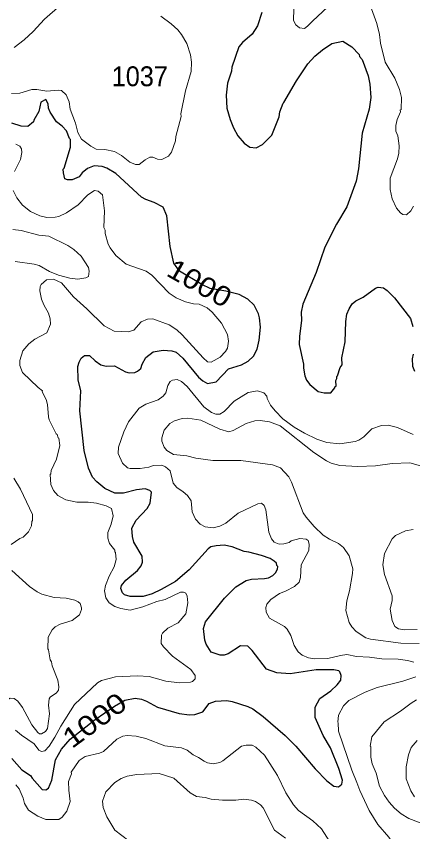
# Model space of a CAD drawing. Extents: x 447.8 to 473.9, y 7733.1 to 7760.8.
# Drawn here: x 462.937 to 464.533, y 7753.226 to 7756.505 of the extents above; entities that cross this region are included whole.
import ezdxf
from ezdxf.enums import TextEntityAlignment as Align

# ---------------------------------------------------------------- set-up
doc = ezdxf.new("R2010")
doc.units = 0
doc.header["$LTSCALE"] = 0.032
doc.layers.add('1', color=7, linetype='Continuous', lineweight=25)
doc.layers.add('2', color=7, linetype='Continuous', lineweight=13)
doc.layers.add('21', color=7, linetype='Continuous')
doc.layers.add('61', color=7, linetype='Continuous')

msp = doc.modelspace()

# ---------------------------------------------------------------- linework, layer by layer
at = {"layer": '1'}
for points in [[(463.9256, 7756.5203), (463.9084, 7756.4667), (463.8873, 7756.4334), (463.8473, 7756.4002), (463.8324, 7756.3825), (463.8049, 7756.3015), (463.803, 7756.2847), (463.7869, 7756.2363), (463.7813, 7756.1882), (463.7841, 7756.1364), (463.7977, 7756.0905), (463.8112, 7756.0567), (463.8288, 7756.0248), (463.8549, 7755.9948), (463.8768, 7755.9794), (463.9032, 7755.9761), (463.9278, 7755.9894), (463.966, 7756.028), (463.9952, 7756.1016), (463.998, 7756.1214), (464.011, 7756.1563), (464.0147, 7756.1584), (464.0653, 7756.2465), (464.1103, 7756.3138), (464.1388, 7756.3448), (464.1696, 7756.3705), (464.2079, 7756.3966), (464.2511, 7756.4048), (464.2874, 7756.3822), (464.3174, 7756.3522), (464.3193, 7756.3441), (464.3295, 7756.3312), (464.3536, 7756.2663), (464.3602, 7756.2331), (464.3649, 7756.1791), (464.3579, 7756.1316), (464.3297, 7756.0349), (464.3146, 7755.8917), (464.3057, 7755.8426), (464.2679, 7755.7396), (464.2266, 7755.67), (464.1795, 7755.577), (464.1444, 7755.4752), (464.0902, 7755.3476), (464.0836, 7755.3151), (464.0851, 7755.2827), (464.0772, 7755.219), (464.0765, 7755.1851), (464.0931, 7755.1063), (464.0932, 7755.09), (464.0993, 7755.0596), (464.1059, 7755.0426), (464.1181, 7755.0248), (464.1527, 7754.9962), (464.1769, 7754.9917), (464.2027, 7754.9917), (464.2193, 7755.0112), (464.2193, 7755.015), (464.2245, 7755.0186), (464.2231, 7755.0403), (464.2277, 7755.0487), (464.2272, 7755.0573), (464.2302, 7755.0593), (464.241, 7755.0924), (464.2486, 7755.1041), (464.2471, 7755.1323), (464.2615, 7755.1962), (464.2641, 7755.2777), (464.2679, 7755.308), (464.2768, 7755.3295), (464.2887, 7755.3489), (464.3038, 7755.361), (464.3339, 7755.3759), (464.3836, 7755.4127), (464.3935, 7755.4166), (464.4154, 7755.4133), (464.4307, 7755.4029), (464.4601, 7755.3736), (464.5237, 7755.2904), (464.5332, 7755.2586)], [(463.6703, 7755.0548), (463.6878, 7755.0393), (463.7072, 7755.0287), (463.7416, 7755.0359), (463.7911, 7755.0879), (463.8432, 7755.1032), (463.8701, 7755.118), (463.892, 7755.1386), (463.9063, 7755.167), (463.9145, 7755.2029), (463.9208, 7755.2551), (463.9162, 7755.2931), (463.9116, 7755.3093), (463.8951, 7755.344), (463.8695, 7755.368), (463.8347, 7755.3861), (463.781, 7755.4002), (463.7169, 7755.4114), (463.6846, 7755.4272), (463.5945, 7755.4811), (463.5715, 7755.5127), (463.556, 7755.5801), (463.5426, 7755.7024), (463.5281, 7755.7384), (463.492, 7755.7572), (463.4581, 7755.7686), (463.4414, 7755.7785), (463.3375, 7755.8731), (463.3015, 7755.8942), (463.2824, 7755.9014), (463.2503, 7755.9039), (463.2243, 7755.8927), (463.2023, 7755.8754), (463.1903, 7755.8598), (463.1617, 7755.8471), (463.1433, 7755.8478), (463.1327, 7755.8524), (463.1268, 7755.8753), (463.1263, 7755.8908), (463.1298, 7755.8945), (463.1553, 7755.9786), (463.1553, 7756.0101), (463.1513, 7756.014), (463.1398, 7756.0447), (463.1224, 7756.0642), (463.0985, 7756.0812), (463.0737, 7756.1193), (463.0671, 7756.136), (463.0654, 7756.1531), (463.0557, 7756.1705), (463.0361, 7756.1595), (463.0275, 7756.1226), (463.0073, 7756.0877), (463.0061, 7756.0806), (462.9838, 7756.0627), (462.9569, 7756.0634), (462.9196, 7756.0762)], [(463.4876, 7755.1561), (463.5285, 7755.1632), (463.5638, 7755.1601), (463.5804, 7755.1542), (463.608, 7755.1306), (463.6703, 7755.0548)], [(464.2284, 7753.8164), (464.2435, 7753.8359), (464.2446, 7753.854), (464.239, 7753.8696), (464.2354, 7753.8728), (464.215, 7753.8775), (464.1442, 7753.8775), (464.039, 7753.8608), (463.9854, 7753.8656), (463.9447, 7753.8792), (463.8861, 7753.9556), (463.8689, 7753.9727), (463.8402, 7753.9737), (463.7899, 7753.9415), (463.7741, 7753.9361), (463.7581, 7753.9361), (463.7222, 7753.9478), (463.7017, 7753.98), (463.696, 7753.996), (463.6901, 7754.0434), (463.699, 7754.0699), (463.7751, 7754.1655), (463.8208, 7754.2113), (463.8622, 7754.2359), (463.8846, 7754.2416), (463.9364, 7754.2439), (463.9529, 7754.2477), (463.9703, 7754.2572), (463.9808, 7754.2671), (463.989, 7754.2819), (463.9895, 7754.2934), (463.9858, 7754.2962), (463.9841, 7754.3056), (463.9753, 7754.3146), (463.9585, 7754.3248), (463.9236, 7754.3375), (463.8727, 7754.3507), (463.854, 7754.353), (463.8059, 7754.3714), (463.7741, 7754.3785), (463.7414, 7754.376), (463.7207, 7754.3714), (463.7098, 7754.3639), (463.6332, 7754.2793), (463.5777, 7754.2327), (463.5209, 7754.1998), (463.4843, 7754.1831), (463.4484, 7754.1717), (463.3959, 7754.1718), (463.3724, 7754.1792), (463.3652, 7754.1873), (463.3579, 7754.204), (463.36, 7754.2163), (463.3784, 7754.2384), (463.4256, 7754.2762), (463.4403, 7754.295), (463.4447, 7754.3097), (463.4439, 7754.3341), (463.4104, 7754.391), (463.4046, 7754.413), (463.4024, 7754.4473), (463.4199, 7754.4795), (463.4634, 7754.5262), (463.4763, 7754.5477), (463.4808, 7754.5919), (463.4751, 7754.5981), (463.4553, 7754.6052), (463.4207, 7754.6012), (463.3682, 7754.5877), (463.3333, 7754.5878), (463.2933, 7754.6066), (463.2607, 7754.6331), (463.2435, 7754.6517), (463.2278, 7754.6881), (463.2109, 7754.7587), (463.1923, 7754.9192), (463.1971, 7754.9997), (463.1868, 7755.0435), (463.185, 7755.0964), (463.1897, 7755.1142), (463.1988, 7755.1305), (463.2112, 7755.1408), (463.2313, 7755.1416), (463.2545, 7755.1195), (463.2771, 7755.1037), (463.2987, 7755.0984), (463.3323, 7755.0991), (463.3763, 7755.0755), (463.3911, 7755.0712), (463.414, 7755.0726), (463.4252, 7755.078), (463.439, 7755.0896), (463.4441, 7755.1059), (463.4583, 7755.1326), (463.4876, 7755.1561)], [(464.5348, 7755.1465), (464.5301, 7755.1282), (464.5317, 7755.0984), (464.5403, 7755.0779)], [(464.1719, 7753.6135), (464.1397, 7753.6856), (464.1397, 7753.7273), (464.1592, 7753.7622), (464.2036, 7753.7923), (464.2284, 7753.8164)], [(462.9196, 7753.52), (462.9589, 7753.4744), (462.9948, 7753.4519), (463.0004, 7753.4409), (463.0414, 7753.3958), (463.0558, 7753.3952), (463.0665, 7753.4018), (463.0805, 7753.4335), (463.0954, 7753.5148), (463.1197, 7753.5575), (463.1535, 7753.5984), (463.255, 7753.6769), (463.3318, 7753.7309), (463.3739, 7753.7554), (463.4153, 7753.7626), (463.4407, 7753.7591), (463.4612, 7753.7511), (463.5056, 7753.7264), (463.5927, 7753.7013), (463.6339, 7753.6956), (463.6552, 7753.6979), (463.6881, 7753.7087), (463.7138, 7753.7417), (463.7393, 7753.7517), (463.7841, 7753.7533), (463.8059, 7753.7502), (463.869, 7753.7299), (463.8893, 7753.7198), (463.9309, 7753.6894), (464.0197, 7753.6128), (464.0626, 7753.5706), (464.1402, 7753.4786), (464.1877, 7753.4304), (464.2158, 7753.4093), (464.2342, 7753.4072), (464.247, 7753.4172), (464.2503, 7753.4335), (464.2356, 7753.48), (464.2014, 7753.5641), (464.1719, 7753.6135)]]:
    msp.add_lwpolyline(points, dxfattribs=at)
at = {"layer": '2'}
for points in [[(463.1136, 7756.5484), (463.0509, 7756.4937), (463.0052, 7756.444), (462.9683, 7756.4103), (462.9286, 7756.3802)], [(464.0549, 7756.5353), (464.0532, 7756.4887), (464.0629, 7756.4715), (464.0777, 7756.4586), (464.0971, 7756.4564), (464.1095, 7756.4653), (464.129, 7756.4865), (464.2108, 7756.562)], [(464.3673, 7756.5354), (464.389, 7756.4767), (464.3993, 7756.4329), (464.4028, 7756.3979), (464.4216, 7756.3206), (464.4605, 7756.2571), (464.4799, 7756.2114), (464.4875, 7756.1792), (464.4859, 7756.1303), (464.4828, 7756.1281), (464.4842, 7756.1206), (464.4701, 7756.0902), (464.4652, 7756.0669), (464.4652, 7756.0429), (464.4724, 7756.0247), (464.4788, 7755.9846), (464.4772, 7755.9551), (464.4722, 7755.9318), (464.4419, 7755.8538), (464.4427, 7755.8086), (464.4508, 7755.7716), (464.4679, 7755.7342), (464.4839, 7755.7144), (464.4925, 7755.7079), (464.5085, 7755.7069), (464.526, 7755.7236), (464.5358, 7755.7412)], [(462.9175, 7756.1951), (462.9507, 7756.1963), (462.9995, 7756.2109), (463.0193, 7756.2109), (463.0597, 7756.2046), (463.105, 7756.2085), (463.1191, 7756.2064), (463.1376, 7756.1902), (463.1497, 7756.1612), (463.1539, 7756.1318), (463.1758, 7756.0758), (463.1842, 7756.0385), (463.199, 7756.0112), (463.2369, 7755.9827), (463.2592, 7755.9706), (463.2932, 7755.9696), (463.3323, 7755.9612), (463.3612, 7755.9455), (463.3941, 7755.9188), (463.4176, 7755.9097), (463.4324, 7755.9096), (463.4561, 7755.9287), (463.4743, 7755.9384), (463.4862, 7755.9383), (463.5061, 7755.9313), (463.5234, 7755.9298), (463.5496, 7755.9434), (463.5613, 7755.9585), (463.5785, 7756.0042), (463.58, 7756.0223), (463.601, 7756.1019), (463.5995, 7756.1132), (463.6188, 7756.2052), (463.6411, 7756.2831), (463.642, 7756.3213), (463.6379, 7756.3504), (463.6233, 7756.3956), (463.6019, 7756.4327), (463.5876, 7756.4512), (463.5604, 7756.4752), (463.519, 7756.5055)], [(462.9295, 7755.881), (462.9534, 7755.9291), (462.9597, 7755.9573), (462.9582, 7755.9718), (462.9516, 7755.9833), (462.9354, 7755.9913)], [(463.2948, 7755.6447), (463.2901, 7755.6566), (463.2916, 7755.7236), (463.2835, 7755.7876), (463.2666, 7755.8024), (463.2517, 7755.8054), (463.2245, 7755.7879), (463.1864, 7755.7466), (463.1388, 7755.7149), (463.1082, 7755.7006), (463.0933, 7755.697), (463.0601, 7755.6964), (463.0319, 7755.7027), (462.994, 7755.7208), (462.9619, 7755.7463), (462.9392, 7755.775), (462.9246, 7755.8047)], [(462.9232, 7755.6483), (462.9562, 7755.6435), (463.0274, 7755.6251), (463.0678, 7755.6207), (463.1451, 7755.5837), (463.1684, 7755.5678), (463.198, 7755.5414), (463.2273, 7755.4946), (463.2307, 7755.4805), (463.2279, 7755.459), (463.2168, 7755.454), (463.1847, 7755.4487), (463.1533, 7755.4524), (463.1069, 7755.464), (463.0712, 7755.4794), (463.0294, 7755.5028), (463.0091, 7755.5088), (462.9325, 7755.52)], [(463.3798, 7755.5088), (463.3376, 7755.543), (463.3147, 7755.574), (463.3074, 7755.5896), (463.2953, 7755.6321), (463.2948, 7755.6447)], [(463.536, 7754.16), (463.5027, 7754.152), (463.4466, 7754.1304), (463.3959, 7754.1173), (463.3575, 7754.1232), (463.3336, 7754.1323), (463.3115, 7754.1465), (463.2976, 7754.1664), (463.2917, 7754.1954), (463.2958, 7754.2157), (463.311, 7754.2538), (463.3315, 7754.2917), (463.3388, 7754.3206), (463.3365, 7754.3492), (463.3335, 7754.3522), (463.3332, 7754.3584), (463.3129, 7754.3858), (463.3061, 7754.4071), (463.3061, 7754.4298), (463.3187, 7754.4632), (463.3268, 7754.4968), (463.3203, 7754.5265), (463.2986, 7754.5373), (463.2599, 7754.5476), (463.2262, 7754.5516), (463.181, 7754.5516), (463.1364, 7754.5612), (463.1043, 7754.578), (463.0872, 7754.5984), (463.0758, 7754.6229), (463.0736, 7754.6627), (463.0765, 7754.666), (463.0777, 7754.6786), (463.0983, 7754.725), (463.1128, 7754.7797), (463.1087, 7754.8088), (463.1057, 7754.8101), (463.1015, 7754.8241), (463.0978, 7754.826), (463.0693, 7754.8826), (463.0662, 7754.8943), (463.0631, 7754.9444), (463.0573, 7754.9644), (463.0418, 7754.9954), (463.0426, 7754.9988), (463.0251, 7755.0122), (462.962, 7755.073), (462.951, 7755.1012), (462.9518, 7755.1208), (462.9639, 7755.1595), (462.9876, 7755.1887), (463.0116, 7755.2069), (463.0595, 7755.2328), (463.0751, 7755.2668), (463.0736, 7755.2888), (463.067, 7755.3118), (463.0478, 7755.3455), (463.0389, 7755.3684), (463.032, 7755.4017), (463.0336, 7755.4194), (463.0372, 7755.4273), (463.0587, 7755.4462), (463.0875, 7755.4489), (463.1187, 7755.4332), (463.1668, 7755.3779), (463.2205, 7755.329), (463.2903, 7755.2603), (463.3306, 7755.2395), (463.3875, 7755.2362), (463.4105, 7755.2438), (463.4393, 7755.277), (463.4654, 7755.2875), (463.4872, 7755.2883), (463.5529, 7755.265), (463.5837, 7755.244), (463.6043, 7755.2249), (463.6896, 7755.1317), (463.7072, 7755.1161), (463.722, 7755.1145), (463.7574, 7755.1344), (463.7795, 7755.1574), (463.7869, 7755.1708), (463.7918, 7755.1993), (463.7867, 7755.2257), (463.7638, 7755.2709), (463.7262, 7755.3162), (463.7058, 7755.3328), (463.6738, 7755.3482), (463.6507, 7755.3497), (463.6177, 7755.3574), (463.5811, 7755.373), (463.5527, 7755.392), (463.4834, 7755.4644), (463.46, 7755.4806), (463.3798, 7755.5088)], [(463.4889, 7754.6983), (463.4708, 7754.6919), (463.4356, 7754.6874), (463.395, 7754.6871), (463.3854, 7754.6901), (463.3643, 7754.7084), (463.3478, 7754.7472), (463.3486, 7754.7729), (463.3706, 7754.8342), (463.3891, 7754.8748), (463.4313, 7754.9301), (463.459, 7754.9455), (463.5082, 7754.9633), (463.5289, 7754.9777), (463.5389, 7754.9911), (463.5476, 7755.0205), (463.5559, 7755.037), (463.5656, 7755.0424), (463.5844, 7755.0453), (463.6016, 7755.037), (463.6256, 7755.0169), (463.6919, 7754.9346), (463.7232, 7754.9123), (463.7398, 7754.906), (463.7559, 7754.906), (463.7738, 7754.9155), (463.8148, 7754.9578), (463.8705, 7754.9931), (463.9084, 7754.9998), (463.9335, 7754.9913), (463.9457, 7754.9781), (463.9475, 7754.9682), (463.9609, 7754.9417), (463.9788, 7754.9186), (464.0105, 7754.887), (464.0561, 7754.8532), (464.0967, 7754.8289), (464.1465, 7754.8054), (464.1868, 7754.792), (464.2394, 7754.7866), (464.3013, 7754.7953), (464.3155, 7754.8007), (464.3366, 7754.8144), (464.369, 7754.8466), (464.4067, 7754.8601), (464.4337, 7754.861), (464.4712, 7754.8515), (464.5349, 7754.8236)], [(464.5734, 7754.6946), (464.5212, 7754.7096), (464.4504, 7754.7071), (464.3825, 7754.6977), (464.312, 7754.6944), (464.2394, 7754.6991), (464.2052, 7754.7083), (464.1855, 7754.7172), (464.1351, 7754.751), (463.9994, 7754.8581), (463.9566, 7754.874), (463.9188, 7754.8795), (463.8977, 7754.8784), (463.8624, 7754.8683), (463.8108, 7754.8393), (463.7922, 7754.8347), (463.7562, 7754.8444), (463.6799, 7754.8818), (463.627, 7754.8899), (463.6053, 7754.8877), (463.5745, 7754.879), (463.5555, 7754.8677), (463.5323, 7754.8413), (463.5225, 7754.8098), (463.5225, 7754.7973), (463.5321, 7754.773), (463.5434, 7754.7586), (463.5702, 7754.7435), (463.6234, 7754.7376), (463.6595, 7754.7287), (463.7284, 7754.7193), (463.8407, 7754.7193), (463.9686, 7754.702), (464.0002, 7754.6895), (464.0336, 7754.6529), (464.045, 7754.6321), (464.0914, 7754.5088), (464.1034, 7754.491), (464.1362, 7754.4533), (464.1727, 7754.4192), (464.1982, 7754.4028), (464.2342, 7754.3849), (464.254, 7754.3693), (464.2774, 7754.3363), (464.2919, 7754.2839), (464.2911, 7754.2644), (464.2784, 7754.1945), (464.268, 7754.1551), (464.2632, 7754.1164), (464.2777, 7754.0672), (464.2875, 7754.0495), (464.3052, 7754.032), (464.3442, 7754.0063), (464.3633, 7754.0001), (464.4856, 7753.9842), (464.5589, 7753.9833)], [(463.5831, 7754.6105), (463.5692, 7754.6278), (463.556, 7754.6775), (463.5375, 7754.6931), (463.5224, 7754.7007), (463.4889, 7754.6983)], [(462.9276, 7754.6481), (462.9541, 7754.6037), (463.003, 7754.5019), (463.003, 7754.4775), (463, 7754.4733), (462.9981, 7754.4569), (462.9867, 7754.4325), (462.9643, 7754.4105), (462.9507, 7754.406), (462.9161, 7754.3807)], [(464.5375, 7753.9079), (464.5123, 7753.9151), (464.4738, 7753.92), (464.4083, 7753.9217), (464.3584, 7753.928), (464.3068, 7753.9304), (464.2683, 7753.9384), (464.2423, 7753.9352), (464.1916, 7753.9225), (464.1393, 7753.9209), (464.1137, 7753.9258), (464.0885, 7753.9365), (464.0717, 7753.9496), (464.0559, 7753.9756), (464.0423, 7754.0153), (464.0272, 7754.0405), (464.0168, 7754.0516), (463.9558, 7754.0848), (463.9435, 7754.1089), (463.9418, 7754.1278), (463.9461, 7754.1415), (463.9615, 7754.1603), (463.9965, 7754.1846), (464.0207, 7754.1932), (464.0576, 7754.212), (464.0753, 7754.2294), (464.0818, 7754.2486), (464.0836, 7754.2996), (464.1142, 7754.3571), (464.1157, 7754.3822), (464.1123, 7754.3968), (464.1046, 7754.4026), (464.0787, 7754.405), (464.0434, 7754.3955), (464.0362, 7754.3897), (464.0143, 7754.3833), (463.9955, 7754.3826), (463.9756, 7754.3904), (463.964, 7754.4045), (463.9534, 7754.431), (463.9422, 7754.5203), (463.9343, 7754.5387), (463.9244, 7754.5468), (463.909, 7754.5449), (463.8303, 7754.5068), (463.7811, 7754.4672), (463.7561, 7754.4543), (463.7299, 7754.4483), (463.6978, 7754.4521), (463.677, 7754.4635), (463.6584, 7754.4837), (463.6453, 7754.5125), (463.641, 7754.5565), (463.6261, 7754.5779), (463.609, 7754.5933), (463.5831, 7754.6105)], [(464.5506, 7754.039), (464.4996, 7754.0386), (464.4763, 7754.0423), (464.4611, 7754.0509), (464.4499, 7754.0762), (464.4422, 7754.1215), (464.45, 7754.1564), (464.4499, 7754.1749), (464.4195, 7754.2612), (464.4123, 7754.2999), (464.4191, 7754.3448), (464.4506, 7754.4043), (464.4635, 7754.4168), (464.5039, 7754.4364), (464.5344, 7754.4419)], [(462.9191, 7754.2765), (462.9904, 7754.2129), (463.0212, 7754.1906), (463.0396, 7754.1815), (463.089, 7754.1683), (463.1377, 7754.1653), (463.1723, 7754.1576), (463.1866, 7754.1505), (463.1939, 7754.1433), (463.2002, 7754.1268), (463.2002, 7754.1192), (463.1921, 7754.0978), (463.1614, 7754.0762), (463.1139, 7754.0612), (463.0939, 7754.0502), (463.0818, 7754.0381), (463.0654, 7754.0092), (463.0639, 7753.9622), (463.067, 7753.9571), (463.0733, 7753.9178), (463.0784, 7753.9094), (463.0818, 7753.8926), (463.104, 7753.835), (463.1089, 7753.8083), (463.1071, 7753.7951), (463.0993, 7753.7848), (463.0738, 7753.7679), (463.0688, 7753.761), (463.0664, 7753.7346), (463.0703, 7753.7004), (463.0631, 7753.6412), (463.0552, 7753.6293), (463.0383, 7753.6203), (463.0304, 7753.6204), (463.0233, 7753.6257), (463.0003, 7753.6561)], [(463.6283, 7754.146), (463.625, 7754.173), (463.6198, 7754.1854), (463.6106, 7754.1893), (463.5982, 7754.1893), (463.536, 7754.16)], [(462.9339, 7753.6348), (462.9587, 7753.6142), (463.0095, 7753.5791), (463.0283, 7753.554), (463.0384, 7753.5482), (463.0522, 7753.5509), (463.069, 7753.5705), (463.0922, 7753.6064), (463.1162, 7753.651), (463.1716, 7753.7375), (463.2641, 7753.8252), (463.2807, 7753.8344), (463.3368, 7753.8496), (463.4254, 7753.8528), (463.4718, 7753.8502), (463.5396, 7753.8316), (463.5943, 7753.8255), (463.6382, 7753.8271), (463.6461, 7753.8296), (463.6571, 7753.841), (463.657, 7753.855), (463.6395, 7753.8791), (463.5656, 7753.9321), (463.5301, 7753.9691), (463.5209, 7753.9834), (463.5223, 7754.0167), (463.5257, 7754.0249), (463.5474, 7754.0453), (463.5882, 7754.0668), (463.6192, 7754.1018), (463.6283, 7754.146)], [(464.6192, 7752.9723), (464.4864, 7753.1315), (464.4364, 7753.204), (464.392, 7753.255), (464.3576, 7753.3119), (464.3206, 7753.3917), (464.3077, 7753.4247), (464.2879, 7753.4731), (464.2343, 7753.6308), (464.2332, 7753.6641), (464.2311, 7753.6666), (464.2347, 7753.6953), (464.2547, 7753.7318), (464.2762, 7753.7542), (464.3421, 7753.7868), (464.3901, 7753.8066), (464.4936, 7753.8318), (464.5449, 7753.8494)], [(463.0003, 7753.6561), (462.9621, 7753.726), (462.9431, 7753.7515), (462.9291, 7753.7622), (462.913, 7753.7629), (462.9052, 7753.7597)], [(464.5488, 7753.7559), (464.5266, 7753.7432), (464.4838, 7753.711), (464.4179, 7753.6675), (464.3685, 7753.6082), (464.361, 7753.57), (464.3641, 7753.5683), (464.3642, 7753.5256), (464.3691, 7753.4997), (464.3863, 7753.4622), (464.3996, 7753.4099), (464.4188, 7753.3715), (464.4376, 7753.3448), (464.4593, 7753.3208), (464.4871, 7753.2981), (464.5175, 7753.2798), (464.584, 7753.2538)], [(462.9355, 7753.4152), (462.9481, 7753.3985), (462.9652, 7753.3616), (462.97, 7753.34), (462.9866, 7753.3129), (463.0241, 7753.2882), (463.0562, 7753.2756), (463.1077, 7753.2757), (463.1222, 7753.2849), (463.1412, 7753.3082), (463.1545, 7753.3471), (463.1482, 7753.3939), (463.1474, 7753.4278), (463.16, 7753.4594), (463.1586, 7753.4654), (463.1899, 7753.512), (463.2141, 7753.5286), (463.2717, 7753.5415), (463.2887, 7753.5493), (463.3418, 7753.5979), (463.3654, 7753.6106), (463.3838, 7753.6131), (463.4195, 7753.6107), (463.459, 7753.6016), (463.5356, 7753.5713), (463.6026, 7753.5641), (463.6248, 7753.5546), (463.649, 7753.5348), (463.6707, 7753.5248), (463.6935, 7753.5095), (463.7073, 7753.5037), (463.7298, 7753.4993), (463.756, 7753.5047), (463.7679, 7753.5106), (463.8442, 7753.5698), (463.8627, 7753.5738), (463.8863, 7753.5737), (463.9014, 7753.5666), (463.9358, 7753.5339), (463.9889, 7753.4519), (464.0223, 7753.3822), (464.0526, 7753.3346), (464.0738, 7753.3111), (464.1314, 7753.2693), (464.1651, 7753.2373), (464.199, 7753.1858)], [(464.5398, 7753.3669), (464.5248, 7753.3904), (464.5069, 7753.4388), (464.5061, 7753.4876), (464.5158, 7753.5359), (464.5267, 7753.5642), (464.5507, 7753.5935)], [(464.0213, 7753.2), (463.9763, 7753.2324), (463.9304, 7753.322), (463.9204, 7753.3336), (463.9005, 7753.3482), (463.884, 7753.3535), (463.8536, 7753.3565), (463.8213, 7753.3526), (463.7678, 7753.3526), (463.7214, 7753.357), (463.6972, 7753.3637), (463.6632, 7753.3679), (463.6374, 7753.3826), (463.5708, 7753.4412), (463.5128, 7753.4599), (463.4227, 7753.4567), (463.3834, 7753.4499), (463.359, 7753.4406), (463.3336, 7753.424), (463.2976, 7753.3866), (463.2837, 7753.3489), (463.2868, 7753.3236), (463.3019, 7753.2854), (463.3339, 7753.2318), (463.3908, 7753.1892)]]:
    msp.add_lwpolyline(points, dxfattribs=at)

# ---------------------------------------------------------------- texts
at = {"layer": '21', "width": 0.95}
msp.add_text('1037', height=0.08, dxfattribs=at).set_placement((463.3213, 7756.2242))
at = {"layer": '61'}
for rotation, width, p in [(330.57, 1.15, (463.6556, 7755.3975)), (36.469, 1.2, (463.2758, 7753.6426))]:
    msp.add_text('1000', height=0.08, rotation=rotation, dxfattribs=dict(at, width=width)).set_placement(p, align=Align.CENTER)

doc.saveas('drawing.dxf')
